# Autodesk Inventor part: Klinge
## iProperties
Created: 2006-12
Part Number: Klinge
Document SubType Name: Modeling
Designer: Kumpf
Manufacturer: Standard
Standards Organization: Custom
Author: Kumpf
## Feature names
1. Extrusion1
